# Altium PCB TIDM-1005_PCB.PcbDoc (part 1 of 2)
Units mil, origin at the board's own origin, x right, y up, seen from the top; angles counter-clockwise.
Board outline 3505 x 2975 mil, 2 copper layers (Top Layer, Bottom Layer), stack 62 mil thick; 159 components, 97 nets, 498 pads, 124 vias.
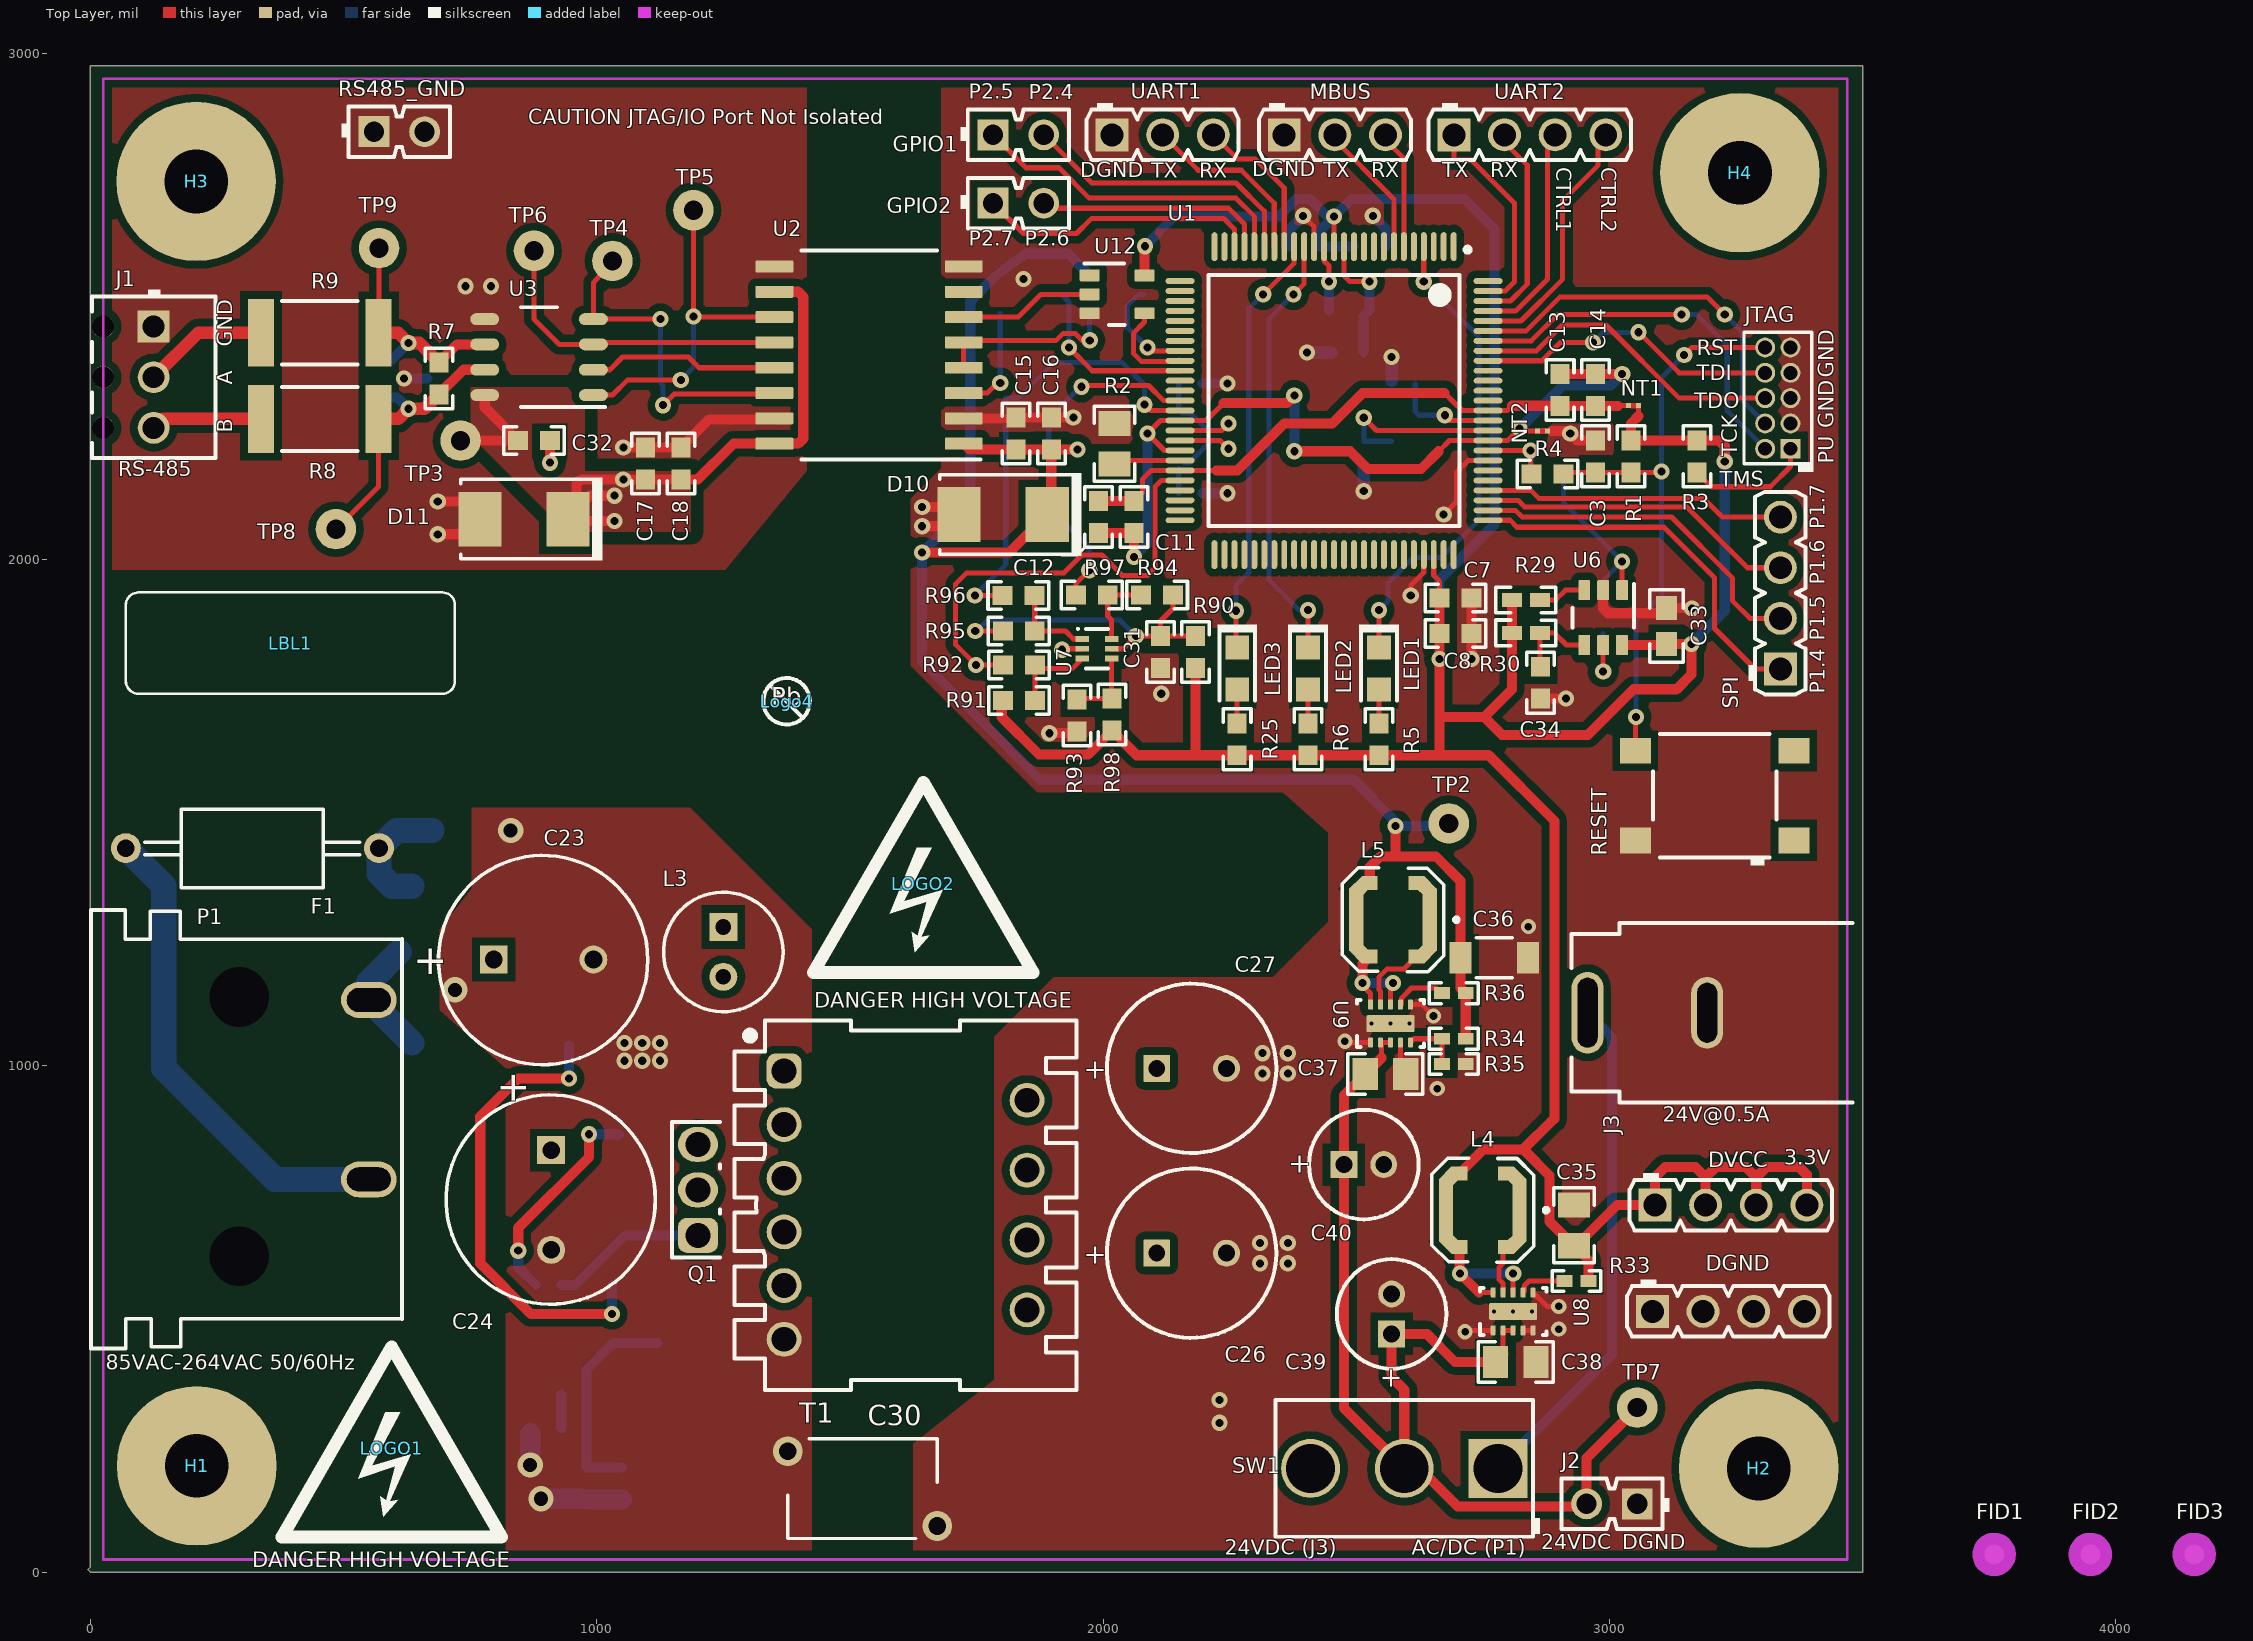
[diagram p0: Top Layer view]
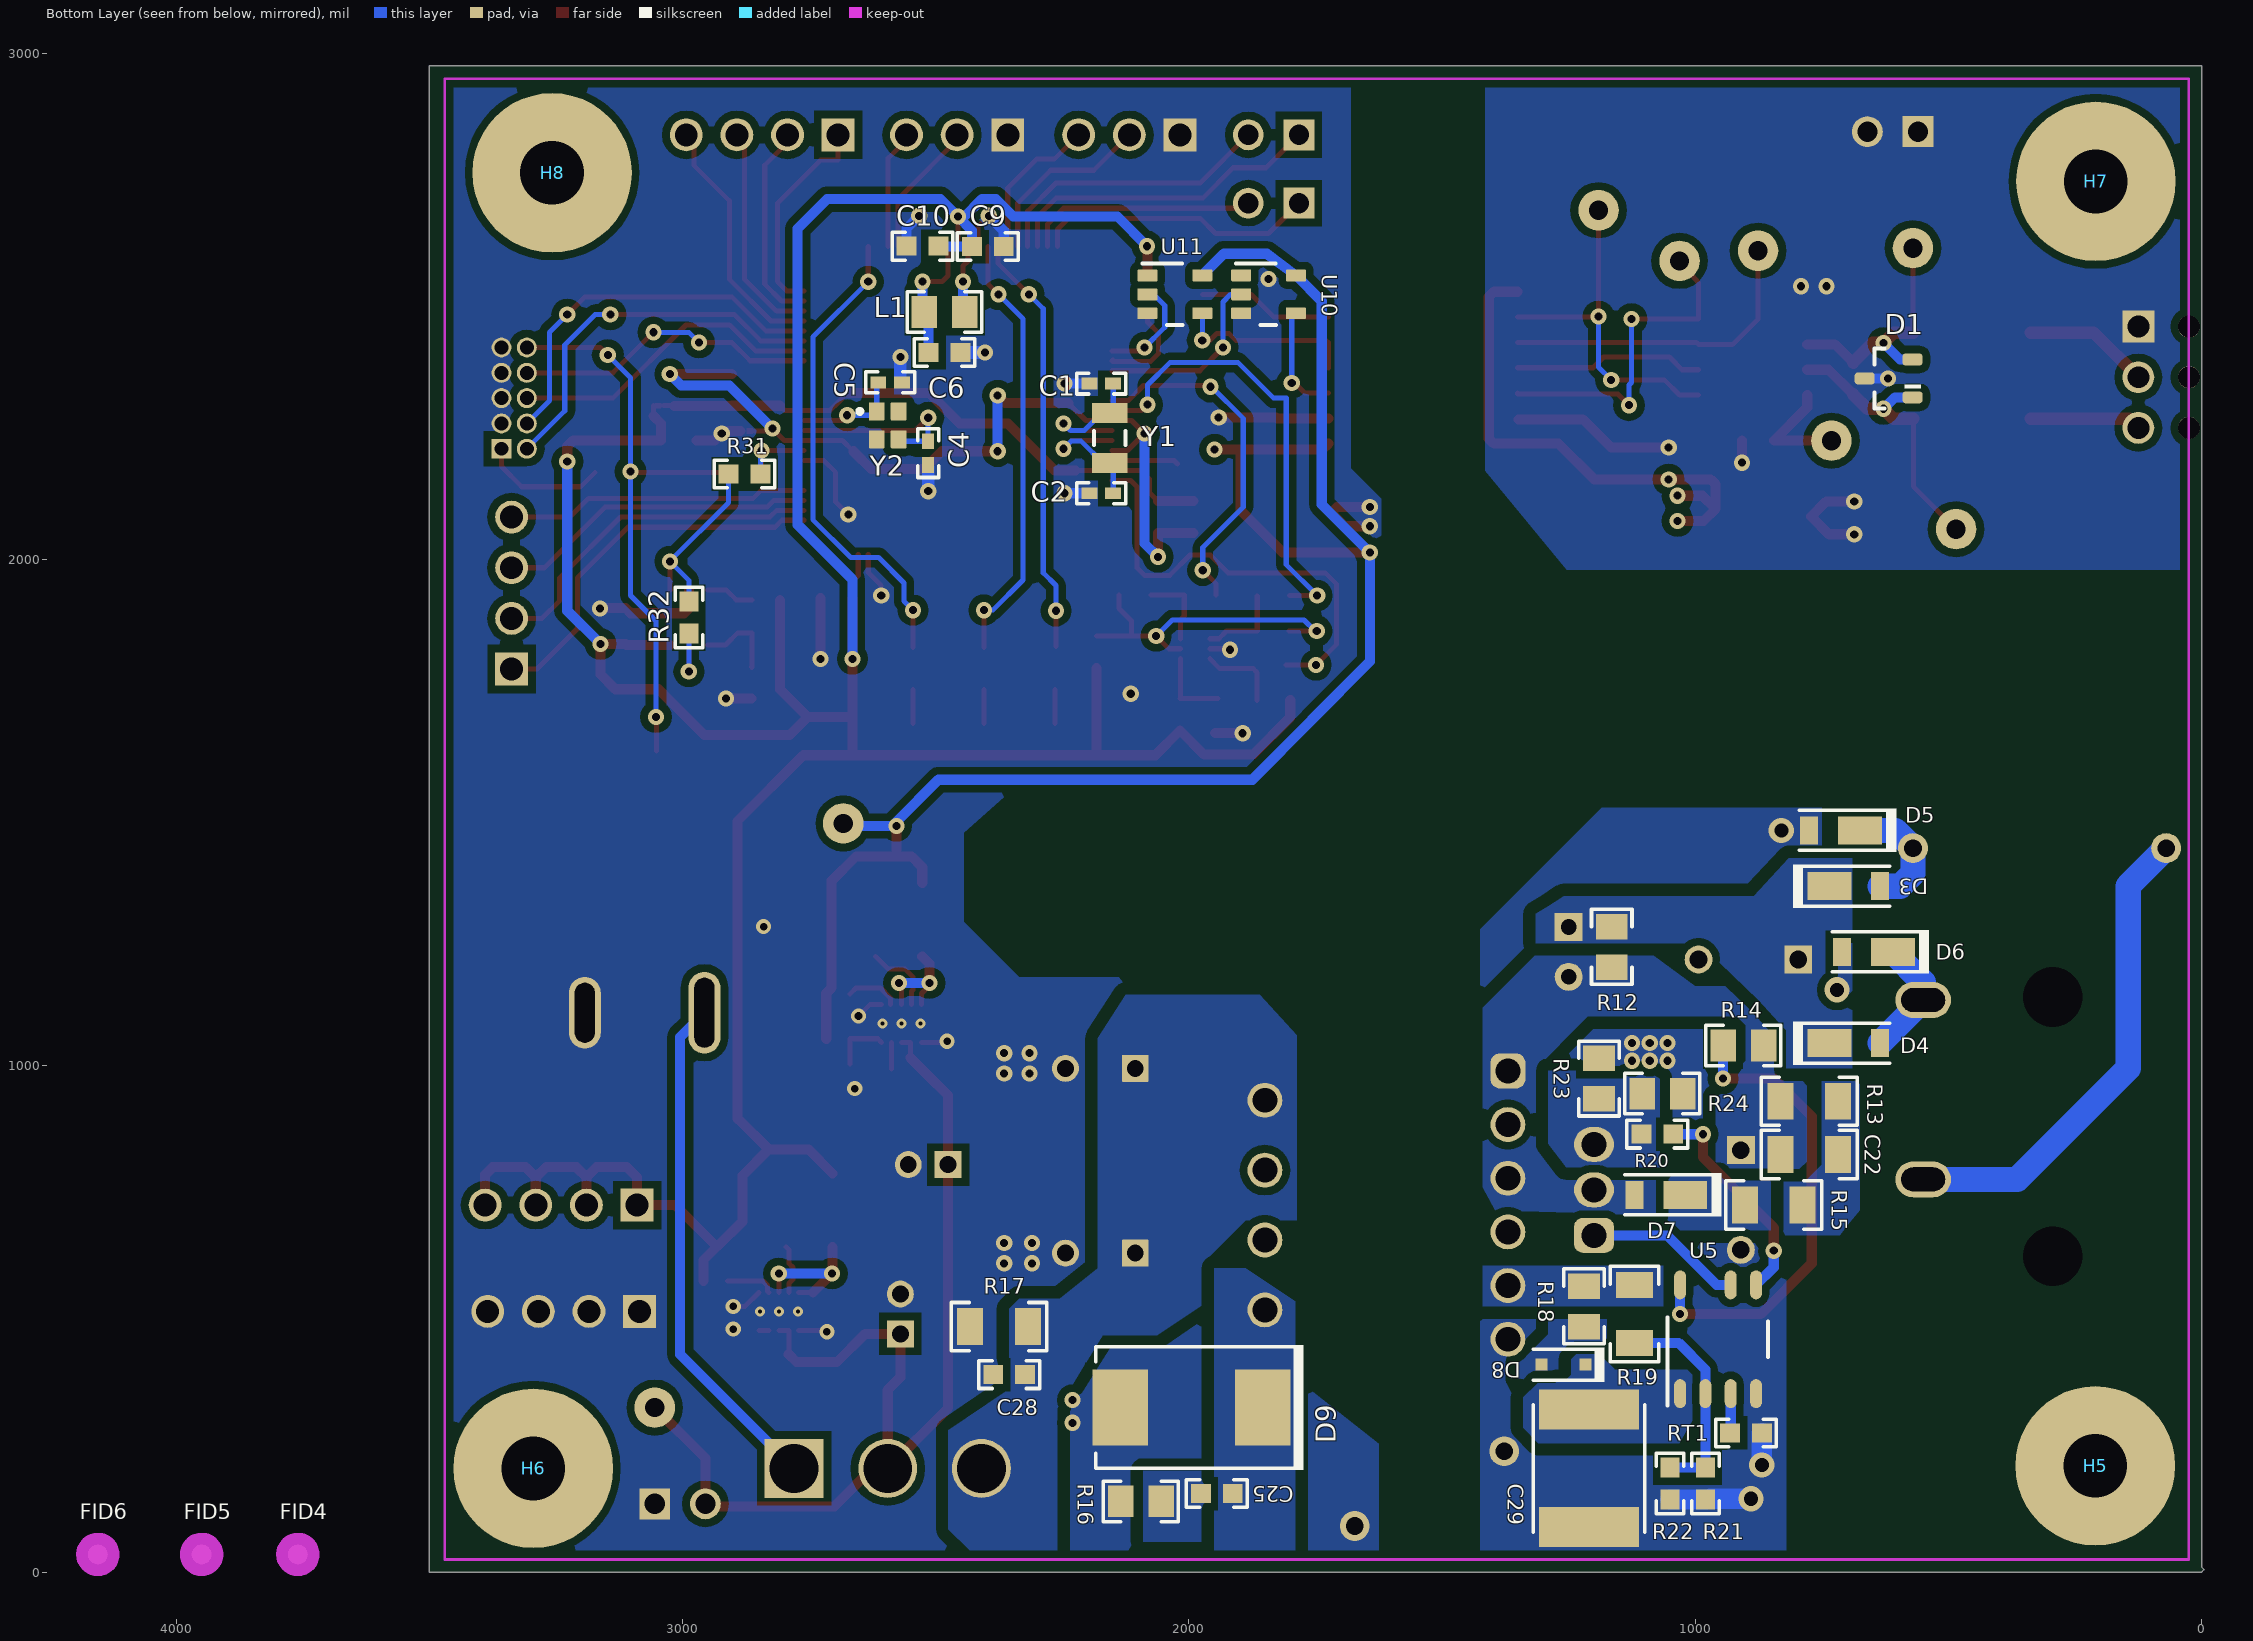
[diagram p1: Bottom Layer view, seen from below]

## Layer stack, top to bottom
Top Solder: solder mask 0.4, Solder Resist, Dk 3.5
Top Layer: signal copper 1.4
Dielectric1: core 59.2, FR-4, Dk 4.8
Bottom Layer: signal copper 1.4
Bottom Solder: solder mask 0.4, Solder Resist, Dk 3.5

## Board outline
-5,5 0,10 0,2975 3500,2975 3500,0 0,0

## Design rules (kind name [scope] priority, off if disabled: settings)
AcuteAngle [All] p1: minimum=4.50000000000000E+0001 checktracksonly=FALSE
AssemblyTestPointUsage [All] p1: valid=2
BoardOutlineClearance BoardOutlineClearance_MountingHoles [OnCopper and InComponentClass('Mounting Holes')] p1: gap=30
BoardOutlineClearance BoardOutlineClearance_Poly [OnCopper and IsPoly] p2: gap=25
BoardOutlineClearance [OnCopper and Not InComponentClass('Logo') and not InComponentClass('FiducialMark') and not InRegion(1000,500,4000,800) and not InPoly] p3: gap=55
Clearance mdViaVia [IsVia vs IsVia] p1: gap=7
Clearance mdPadVia [IsPad vs IsVia] p2: gap=7
Clearance mdPadPad [IsPad vs IsPad] p3: gap=7
Clearance mdWireVia [(InLayerClass('Signal Layers') AND IsTrack) vs IsVia] p4: gap=7
Clearance mdWirePad [(InLayerClass('Signal Layers') AND IsTrack) vs IsPad] p5: gap=7
Clearance mdWireWire [(InLayerClass('Signal Layers') AND IsTrack) vs (InLayerClass('Signal Layers') AND IsTrack)] p6: gap=7
Clearance [All] p7: gap=7 except(15: Arc-Poly Track-Poly SMDPad-Poly THPad-Poly Via-Poly Fill-Poly; 25: Poly-Poly)
ComponentClearance ComponentClearance_MountingHoles_FiducialMarks [InComponentClass('Mounting Holes') vs InComponentClass('FiducialMark')] p1: gap=50 collisioncheckmode=3 verticalgap=10 showdistances=FALSE
ComponentClearance ComponentClearance_Shunt [InComponentClass('Header') vs InComponentClass('Shunt')] p2: gap=0 collisioncheckmode=3 verticalgap=0 showdistances=FALSE
ComponentClearance ComponentClearance_Logo [InComponentClass('Logo')] p3: gap=0 collisioncheckmode=3 verticalgap=0 showdistances=FALSE
ComponentClearance ComponentClearance_ScrewToNut [(HasFootprint('NY PMS 440 0025 PH')) vs (HasFootprint('Keystone_1902C'))] p4: gap=5 collisioncheckmode=3 verticalgap=10 showdistances=FALSE
ComponentClearance ComponentClearance_MountingHoles [InComponentClass('Mounting Holes')] p5: gap=0 collisioncheckmode=3 verticalgap=100000 showdistances=FALSE
ComponentClearance ComponentClearance_SmallPassives [HasFootprint('0201*') or HasFootprint('0402*') or HasFootprint('0508') or HasFootprint('0603*') or HasFootprint('0612') or HasFootprint('0805*') or HasFootprint('0815*') or HasFootprint('0830*') or HasFootprint('1206*') or HasFootprint('1210*') or HasFootprint('1808*') or HasFootprint('1812*') or HasFootprint('1825*') or HasFootprint('2010*') or HasFootprint('2220*') or HasFootprint('2225*') or HasFootprint('2512*') or HasFootprint('2728*') or HasFootprint('3518*') vs HasFootprint('0201*') or HasFootprint('0402*') or HasFootprint('0508') or HasFootprint('0603*') or HasFootprint('0612') or HasFootprint('0805*') or HasFootprint('0815*') or HasFootprint('0830*') or HasFootprint('1206*') or HasFootprint('1210*') or HasFootprint('1808*') or HasFootprint('1812*') or HasFootprint('1825*') or HasFootprint('2010*') or HasFootprint('2220*') or HasFootprint('2225*') or HasFootprint('2512*') or HasFootprint('2728*') or HasFootprint('3518*')] p6: gap=14.96 collisioncheckmode=3 verticalgap=10 showdistances=FALSE
ComponentClearance ComponentClearance_THtoSMT [IsThruComponent vs IsSMTComponent] p7: gap=40 collisioncheckmode=3 verticalgap=30 showdistances=FALSE
ComponentClearance ComponentClearance_THtoTH [IsThruComponent vs IsThruComponent] p8: gap=30 collisioncheckmode=3 verticalgap=30 showdistances=FALSE
ComponentClearance [All] p9: gap=30 collisioncheckmode=3 verticalgap=10 showdistances=FALSE
DiffPairsRouting [All] p1: maxlimit=100 minlimit=10 mostfreqgap=10 toplayer_minwidth=15 toplayer_maxwidth=15 toplayer_prefwidth=15 bottomlayer_minwidth=15 bottomlayer_maxwidth=15 bottomlayer_prefwidth=15 maxuncoupledlength=1000
FabricationTestPointUsage TestPointUsage [All] p1: valid=2 allowmultiple=FALSE
FabricationTestpoint Testpoint [All] p1: side=3 testpointundercomponent=TRUE minsize=40 maxsize=100 preferedsize=60 minholesize=0 maxholesize=40 preferedholesize=32 testpointgrid=1 allowsidetop=TRUE allowsidebottom=TRUE usegrid=TRUE gridtolerance=0.01
FanoutControl Fanout_LCC [IsLCC] p1: bgadir=Out bgaviamode=Centered fanoutstyle=Auto fanoutdirection=Alternating viagrid=1 // Fanout_LCC (Default Rule)
FanoutControl Fanout_BGA [IsBGA] p2: bgadir=Out bgaviamode=Centered fanoutstyle=Auto fanoutdirection=Alternating viagrid=1 // Fanout_BGA (Default Rule)
FanoutControl Fanout_Default [All] p4: bgadir=Out bgaviamode=Centered fanoutstyle=Auto fanoutdirection=Alternating viagrid=1 // Fanout_Default (Default Rule)
FanoutControl Fanout_Small [(CompPinCount < 5)] p5: bgadir=Out bgaviamode=Centered fanoutstyle=Auto fanoutdirection=OutThenIn viagrid=1 // Fanout_Small (Default Rule)
Height [All] p1: minheight=0 maxheight=1200 prefheight=500
HoleSize [All] p1: absolutevalues=TRUE maxlimit=251 minlimit=7.87 maxpercent=80.000 minpercent=20.000
MinimumAnnularRing MinimumAnnularRing_ThermalPadVias [IsVia and InAnyComponent] p1: minimumring=5.91
MinimumAnnularRing [All] p2: minimumring=5
MinimumSolderMaskSliver MinimumSolderMaskSliver_Logo [InComponentClass('Logo') vs InComponentClass('Logo')] p1: minsoldermaskwidth=0.7
MinimumSolderMaskSliver [All] p2: minsoldermaskwidth=3.94
PlaneConnect [All] p1: planeconnectstyle=Direct reliefexpansion=10 reliefentries=4 reliefconductorwidth=10 reliefairgap=10
PolygonConnect PolygonConnect_Via [All vs IsVia] p1: connectstyle=Direct reliefconductorwidth=10 reliefentries=4 polygonreliefangle="90 Angle" airgapwidth=10
PolygonConnect PolygonConnect_1 [All] p2: connectstyle=Direct reliefconductorwidth=10 reliefentries=4 polygonreliefangle="90 Angle" airgapwidth=10
RoutingVias ThermalPadVias [IsVia and InAnyComponent] p1: holewidth=7.87 width=19.68 viastyle="Through Hole" minholewidth=7.87 minwidth=19.68 maxholewidth=12.99 maxwidth=23.62
RoutingVias [All] p2: holewidth=16 width=34 viastyle="Through Hole" minholewidth=7.87 minwidth=26 maxholewidth=40 maxwidth=65
SilkToBoardRegionClearance [Not ((IsComment or IsDesignator) And (Hide <> 'False')) and not InRegion(1000,500,4000,800)] p1:
SilkToSilkClearance SilkToSilkClearance_Pb-FreeLogo [(HasFootprint('Pb-Free_Overlay_Medium') OR HasFootprint('Pb-Free_Overlay_Small')) vs (HasFootprint('Pb-Free_Overlay_Medium') OR HasFootprint('Pb-Free_Overlay_Small'))] p1: silktosilkclearance=0
SilkToSilkClearance [All] p2: silktosilkclearance=4
SilkToSolderMaskClearance SilkToComponentPadClearance [(IsPad or IsFill or IsRegion) and InAnycomponent] p1: minsilkscreentomaskgap=3 clearancetoexposedcopper=TRUE
SilkToSolderMaskClearance "Silk to Solder Mask Opening" [All] p2: minsilkscreentomaskgap=1 clearancetoexposedcopper=FALSE
SolderMaskExpansion [All] p1: expansion=1.97
Width Width_1 [(InNet('24VDC') OR InNet('NetD6_2') OR InNet('NetD6_1') OR InNet('NetQ1_3') OR InNet('NetR18_1') OR InNet('NetQ1_1') OR InNet('NetR17_2') OR InNet('NetR16_2') OR InNet('NetR12_2')OR InNet('NetC22_1') OR InNet('NetC25_2') OR InNet('NetJ11_1') OR InNet('NetC19_1') OR InNet('NetC19_2') OR InNet('NetC29_2')) OR InNet('NetC25_1')] p1: maxlimit=40 minlimit=20 preferedwidth=20 minimp=50.000000 maximp=50.000000 favimp=50.000000
Width Width_PWR [InNet('PGND') OR InNet('NetF1_2') OR InNet('NetD2_2') OR InNet('NetD3_2') OR InNet('NetC23_1') OR InNet('NetC22_2') OR InNet('NetD4_2') OR InNet('NetD7_2')] p2: maxlimit=50 minlimit=30 preferedwidth=50 minimp=50.000000 maximp=50.000000 favimp=50.000000
Width Width_VCC [InNet('24VDCIN') OR InNet('24VDCOUT')OR InNet('DVCC')OR InNet('AVCC')OR InNet('5VDC') OR InNet('NetC17_1')OR InNet('NetR18_2') or InNet('NetR20_1') or InNet('NetR14_2')] p3: maxlimit=50 minlimit=10 preferedwidth=20 minimp=50.000000 maximp=50.000000 favimp=50.000000
Width [All] p4: maxlimit=40 minlimit=10 preferedwidth=10 minimp=50.000000 maximp=50.000000 favimp=50.000000
14 further rules are at their usual default settings.

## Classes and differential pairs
component class TIDM-1005_2: C15 C16 C17 C18 C31 C32 C33 C34 D1 D10 D11 J1 R7 R8 R9 R29 R30 R32 R90 R91 R92 R93 R94 R95 R96 R97 R98 RS485_GND TP2 TP3 TP4 TP5 TP6 TP8 TP9 U2 U3 U6 U7 U10 U11 U12
component class TIDM-1005-EVM_Hardware: !PCB FID1 FID2 FID3 FID4 FID5 FID6 H1 H2 H3 H4 H5 H6 H7 H8 LBL1 LOGO1 LOGO2 Logo4 ZZ1 ZZ2 ZZ3 ZZ4
component class "Mounting Holes": H1 H2 H3 H4
component class Label: LBL1
component class FiducialMark: FID1 FID2 FID3 FID4 FID5 FID6
component class AssemblyNote: ZZ1 ZZ2 ZZ3 ZZ4
component class TIDM-1005_3: C22 C23 C24 C25 C26 C27 C28 C29 C30 C35 C36 C37 C38 C39 C40 D3 D4 D5 D6 D7 D8 D9 F1 J2 J3 L3 L4 L5 P1 Q1 R12 R13 R14 R15 R16 R17 R18 R19 R20 R21 R22 R23 R24 R33 R34 R35 R36 RT1 SW1 T1 TP7 U5 U8 U9
component class Header: DGND DVCC GPIO1 GPIO2 J2 J9 J10 JTAG JTAG1 MBUS MBUS1 RS485_GND SPI SPI1 UART1 UART2
component class TIDM-1005_1: C1 C2 C3 C4 C5 C6 C7 C8 C9 C10 C11 C12 C13 C14 DGND DVCC GPIO1 GPIO2 J9 JTAG JTAG1 L1 LED1 LED2 LED3 MBUS NT1 NT2 R1 R2 R3 R4 R5 R6 R25 R31 RESET SPI U1 UART1 UART2 Y1 Y2

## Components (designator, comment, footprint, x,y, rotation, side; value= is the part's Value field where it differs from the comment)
C1 "C1005C0G1H220J050BA" 0402 2173.2,2347.47 r180 bottom
C2 "C1005C0G1H220J050BA" 0402 2173.2,2130.93 r180 bottom
C3 "06033C104KAT2A" 0603 2972.8,2203.81 r90 top
C4 "C1005C0G1H220J050BA" 0402 2515,2210 r90 bottom
C5 "C1005C0G1H220J050BA" 0402 2590,2350 r0 bottom
C6 "GRM188R71E474KA12D" 0603 2482.8,2408.81 r180 bottom
C7 "GRM188R6YA475KE15D" 0603 2696.3,1923.81 r180 top
C8 "GCM188R71H104KA57D" 0603 2696.3,1853.81 r0 top
C9 "GRM188R6YA475KE15D" 0603 2397.25,2617.94 r0 bottom
C10 "GCM188R71H104KA57D" 0603 2526.3,2618.81 r0 bottom
C11 "GRM188R6YA475KE15D" 0603 2061.3,2083.81 r90 top
C12 "GCM188R71H104KA57D" 0603 1991.3,2083.81 r270 top
C13 "GRM188R6YA475KE15D" 0603 2902.85,2334.79 r270 top
C14 "GCM188R71H104KA57D" 0603 2972.85,2334.79 r90 top
C15 "C0603C104J4RACTU" 0603 1827.8,2248.81 r90 top
C16 "C0603C106M9PACTU" 0603 1897.8,2248.81 r270 top
C17 "C0603C104J4RACTU" 0603 1096.09,2189.83 r90 top
C18 "C0603C106M9PACTU" 0603 1166.09,2189.83 r270 top
C22 "C3216C0G2J471J085AA" 1206 775,825 r0 bottom
C23 "UCS2G100MPD1TD" CAPPRD500W60D1000H2000 895,1210 r0 top
C24 "UCS2G100MPD1TD" CAPPRD500W60D1000H2000 910,735 r270 top
C25 "GRM188R72E221KW07D" 0603 1945,155 r180 bottom
C26 "UHE1V221MPD1TD" Nichicon_800x1500 2175,630 r0 top
C27 "UHE1V221MPD1TD" Nichicon_800x1500 2175,995 r0 top
C28 "0603YC104JAT2A" 0603 2355,390 r0 bottom
C29 "CKG57NX5R1E476M500JH" CKG57N 1210,205 r90 bottom
C30 "VY2471K29Y5SS63V7" VY2_750x500 1525,165 r180 top
C31 "06033C104JAT2A" 0603 2113.66,1817.31 r90 top
C32 "C0603C104J4RACTU" 0603 876.09,2234.83 r0 top
C33 "06033C104JAT2A" 0603M 3112.8,1868.81 r270 top
C34 "06035A151JAT2A" 0603 2864.29,1756.8 r270 top
C35 "GRM21BR60J226ME39L" 0805_HV 2930,685 r90 top
C36 "GRM31CR61A226KE19L" 1206_180 2772.72,1213.54 r0 top
C37 "GRM21BR61E225KA12L" 0805_HV 2557.72,983.54 r180 top
C38 "GRM21BR61E225KA12L" 0805_HV 2815,415 r180 top
C39 "ECA1HM220" Panasonic_500x1100 2570,510 r90 top
C40 "ECA1HM220" Panasonic_500x1100 2515,805 r0 top
D1 "CDSOT23-SM712" SOT-23 618.16,2357.72 r0 bottom
D3 "DFLR1600-7" PowerDI123 685,1355 r180 bottom
D4 "DFLR1600-7" PowerDI123 685,1045 r180 bottom
D5 "DFLR1600-7" PowerDI123 725,1465 r0 bottom
D6 "DFLR1600-7" PowerDI123 660,1225 r0 bottom
D7 "DFLR1600-7" PowerDI123 1070,745 r0 bottom
D8 "BAS20HT1G" SOD-323 1260,410 r0 bottom
D9 "MBRS3201T3G" SMC 1995,325 r0 bottom
D10 "1SMB5919BT3G" SMB 1802.8,2088.81 r180 top
D11 "1SMB5919BT3G" SMB 856.09,2079.83 r180 top
DGND "61300411121" WURTH_61300411121 3235,515 r0 top
DVCC "61300411121" WURTH_61300411121 3240,725 r0 top
F1 "0263002.MAT1L" FUSE_263 320,1430 r180 top
FID1 "Fiducial" Fiducial10-20 3760,35 r0 top
FID2 "Fiducial" Fiducial10-20 3950,35 r0 top
FID3 "Fiducial" Fiducial10-20 4155,35 r0 top
FID4 "Fiducial" Fiducial10-20 3760,35 r180 bottom
FID5 "Fiducial" Fiducial10-20 3950,35 r180 bottom
FID6 "Fiducial" Fiducial10-20 4155,35 r180 bottom
GPIO1 "TSW-102-07-T-S" Samtec_TSW-102-07-T-S 1832.8,2838.81 r0 top
GPIO2 "TSW-102-07-T-S" Samtec_TSW-102-07-T-S 1832.8,2703.81 r0 top
H1 "NY PMS 440 0025 PH" "NY PMS 440 0025 PH"#1 210,210 r0 top
H2 "NY PMS 440 0025 PH" "NY PMS 440 0025 PH"#1 3295,205 r0 top
H3 "NY PMS 440 0025 PH" "NY PMS 440 0025 PH"#2 870,3220 r0 top
H4 "NY PMS 440 0025 PH" "NY PMS 440 0025 PH"#1 3257.8,2763.81 r0 top
H5 "1902C" Keystone_1902C#1 210,210 r180 bottom
H6 "1902C" Keystone_1902C#1 3295,205 r180 bottom
H7 "1902C" Keystone_1902C#2 865,3185 r180 bottom
H8 "1902C" Keystone_1902C#1 3257.8,2763.81 r180 bottom
J1 "1725669" Phoenix_1725669 125,2360 r270 top
J2 "TSW-102-07-T-S" Samtec_TSW-102-07-T-S 3005,135 r180 top
J3 "PJ-037AH" CUI_PJ-037AH 3075,1105 r90 top
JTAG "GRPB052VWVN-RC" CONN_GRPB052VWVN-RC 3332.8,2318.81 r90 top
L1 "LQM21PN4R7NGR" IND_LQM18P_FH 2482.8,2488.81 r0 bottom
L3 "7447462221" WE-TI_5075 1250,1225 r270 top
L4 "LPS4018-103MRB" LPS4018 2750,715 r180 top
L5 "LPS4018-103MRB" LPS4018 2572.72,1288.54 r180 top
LBL1 "Size: 0.65\" x 0.20 \"" Label_650x200 395,1835 r0 top
LED1 "LTST-C170KRKT" LED_LTST-C170_Red 2545,1785 r90 top
LED2 "LTST-C170KSKT" LED_LTST-C170 2405,1785 r90 top
LED3 "LTST-C170TBKT" LTST-C170TBKT_Blue 2265,1785 r90 top
LOGO1 "DANGER HIGH VOLTAGE" IEC_HighVoltage_Medium 595,245 r0 top
LOGO2 "DANGER HIGH VOLTAGE" IEC_HighVoltage_Medium 1645,1360 r0 top
Logo4 "Pb-Free Symbol" Pb-Free_Overlay_Small 1375,1720 r0 top
MBUS "61300311121" WURTH_61300311121 2457.8,2838.81 r0 top
NT1 "Net-Tie" Net-Tie_10mil 3047.8,2303.81 r180 top net-tie
NT2 "Net-Tie" Net-Tie_10mil 2867.8,2253.81 r180 top net-tie
P1 "770W-X2/10" CONN_AC_770W-SERIES 420,880 r90 top
Q1 "STD5NM60-1" IPAK 1200,755 r90 top
R1 "ERA-3AEB104V" 0603 3042.8,2203.81 r90 top
R2 "RG2012P-913-B-T5" 0805_HV 2022.8,2228.81 r90 top
R3 "ERJ-3EKF1001V" 0603 3172.8,2203.81 r90 top
R4 "CRCW06030000Z0EA" 0603 2877.8,2168.81 r180 top
R5 "ERA-3AEB101V" 0603 2544.93,1645 r270 top
R6 "ERA-3AEB101V" 0603 2405,1645 r270 top
R7 "CRCW0603120RJNEA" 0603 688.16,2357.72 r90 top
R8 "CRCW251210R0FKEG" 2512 453.16,2277.72 r180 top
R9 "CRCW251210R0FKEG" 2512 453.16,2447.72 r180 top
R12 "MCU08050C1002FP500" 0805_HV 1165,1235 r270 bottom
R13 "RC1206FR-07330KL" 1206 775,930 r180 bottom
R14 "MCU08050C1003FP500" 0805_HV 905,1040 r0 bottom
R15 "RC1206FR-07120RL" 1206 845,725 r0 bottom
R16 "ERJ-P6WF47R0V" 0805_HV 2095,140 r0 bottom
R17 "ERJ-8ENF3902V" 1206 2375,485 r0 bottom
R18 "RC0805FR-072RL" 0805_HV 1220,525 r90 bottom
R19 "RC1206FR-07110KL" 1206 1120,510 r270 bottom
R20 "MCT06030C2200FP500" 0603 1075,865 r0 bottom
R21 "MCT06030C3302FP500" 0603 980,175 r270 bottom
R22 "CRCW0603560KFKEA" 0603 1050,175 r270 bottom
R23 "RC0805FR-072RL" 0805_HV 1190,975 r90 bottom
R24 "RL1220S-2R2-F" 0805_HV 1065,945 r180 bottom
R25 "ERA-3AEB101V" 0603 2264.93,1645 r270 top
R29 "CRCW040210K0FKED" 0402M 2835.24,1920.3 r180 top
R30 "CRCW040210K0FKED" 0402M 2835.24,1855.3 r180 top
R31 "CRCW06030000Z0EA" 0603 2877.8,2168.81 r180 bottom
R32 "CRCW06030000Z0EA" 0603 2987.8,1885.3 r270 bottom
R33 "CRCW0402100KFKED" 0402 2935,575 r0 top
R34 "CRCW04022M00FKED" 0402 2692.72,1053.54 r180 top
R35 "CRCW0402383KFKED" 0402 2692.72,1003.54 r0 top
R36 "CRCW0402100KFKED" 0402 2692.72,1143.54 r0 top
R90 "RC0603JR-070RL" 0603 2182.8,1817.31 r270 top
R91 "CRCW060310K0JNEA" 0603 1833.9,1721.9 r180 top
R92 "RC0603JR-070RL" 0603 1833.9,1791.9 r180 top
R93 "RC0603JR-070RL" 0603 1948.9,1691.9 r270 top
R94 "RC0603FR-074K7L" 0603 2106.8,1929.81 r0 top
R95 "RC0603FR-074K7L" 0603 1833.66,1858.81 r180 top
R96 "CRCW060310R0FKEA" 0603 1832.8,1928.81 r180 top
R97 "CRCW060310R0FKEA" 0603 1977.8,1929.81 r180 top
R98 "RC0603FR-074K7L" 0603 2017.8,1693.81 r270 top
RESET "430182080816" SW_430182080816 3207.8,1533.81 r180 top
RS485_GND "TSW-102-07-T-S" Samtec_TSW-102-07-T-S 610,2845 r0 top
RT1 "NCP18WF104F12RB" 0603 900,275 r180 bottom
SPI "61300411121" WURTH_61300411121 3337.8,1933.81 r90 top
SW1 "100SP3T1B1M1QEH" SW_100SP3T1B1M1QEH 2595,205 r180 top
T1 "RLTI-1223" Renco_RLTI-1223 1610,725 r0 top
TP2 "TESTPOINT" TESTPOINT 2682.8,1478.81 r0 top
TP3 "TESTPOINT" TESTPOINT 731.09,2234.83 r0 top
TP4 "TESTPOINT" TESTPOINT 1031.09,2589.83 r0 top
TP5 "TESTPOINT" TESTPOINT 1191.09,2689.83 r0 top
TP6 "TESTPOINT" TESTPOINT 876.09,2609.83 r0 top
TP7 "TESTPOINT" TESTPOINT 3055,325 r0 top
TP8 "TESTPOINT" TESTPOINT 485,2060 r0 top
TP9 "TESTPOINT" TESTPOINT 570,2615 r0 top
U1 "MSP432P401RIPZR" PZ0100A_N 2456.3,2313.81 r270 top
U2 "ISOW7841DWR" DW0016B_N 1537.8,2403.81 r180 top
U3 "THVD1500DR" D0008A_N 886.09,2399.83 r180 top
U5 "UCC28711DR" D0007A_N 955,460 r90 bottom
U6 "TPS3808G01DBVR" DBV0006A_N 2987.8,1885.3 r270 top
U7 "TMP102AIDRL" DRL0006A_N 1987.8,1823.81 r0 top
U8 "TPS62177DQCR" DQC0010A 2810,515 r90 top
U9 "TPS62175DQCR" DQC0010A 2567.72,1083.54 r90 top
U10 "SN74LV1T34DBVR" DBV0005A_N 1842.8,2523.81 r180 bottom
U11 "SN74LV1T34DBVR" DBV0005A_N 2027.8,2523.81 r180 bottom
U12 "SN74LV1T34DBVR" DBV0005A_N 2027.8,2523.81 r0 top
UART1 "61300311121" WURTH_61300311121 2117.8,2838.81 r0 top
UART2 "61300411121" WURTH_61300411121 2842.8,2838.81 r0 top
Y1 "FC-135R 32.7680KA-A3" Epson_FC-135 2156.43,2239.99 r270 bottom
Y2 "CX2016DB48000H0FLJC1" Kyocera_CX2016DB 2595,2265 r180 bottom
ZZ1 "This Assembly Note is for PCB labels only" AssemblyNoteLabel 30,3735 r0 top
ZZ2 "These assemblies are ESD sensitive, ESD precautions shall be observed." AssemblyNote 30,3615 r0 top
ZZ3 "These assemblies must be clean and free from flux and all contaminants. Use of no clean flux is not acceptable." AssemblyNote 30,3485 r0 top
ZZ4 "These assemblies must comply with workmanship standards IPC-A-610 Class 2, unless otherwise specified." AssemblyNote 30,3350 r0 top

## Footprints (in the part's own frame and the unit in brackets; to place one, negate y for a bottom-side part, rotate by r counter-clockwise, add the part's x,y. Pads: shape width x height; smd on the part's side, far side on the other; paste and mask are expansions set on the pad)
0402 [mm] "0402 from SM-752 data"
  rect 0.8x0.6 smd: 1(-0.6,0) 2(0.6,0)
  silkscreen extent -1.22,-0.52 1.22,0.52, body extent -0.55,-0.3 0.55,0.3, height 0.6
0402M [mm] "0402 from SM-752 data"
  rect 1x0.7 smd: 1(-0.7,0) 2(0.7,0)
  silkscreen extent -1.5,-0.64 1.51,0.65, body extent -0.55,-0.3 0.55,0.3, height 0.6
0603 [mm] "0603 from SM-752 data"
  rect 1x0.95 smd: 1(-0.8,0) 2(0.8,0)
  silkscreen extent -1.52,-0.69 1.52,0.69, body extent -0.87,-0.47 0.87,0.47, height 1
0603M [mm] "0603 from SM-752 data"
  rect 1.2x1.05 smd: 1(-0.9,0) 2(0.9,0)
  silkscreen extent -1.82,-0.84 1.82,0.84, body extent -0.87,-0.47 0.87,0.47, height 1
0805_HV [mil] "0805 with 30mil clearance between pads"
  rect 50x63 smd: 1(-40,0) 2(40,0)
  silkscreen extent -74,-40 74,40, body extent -43,-29 43,29, height 57
1206 [mm] "1206 from SM-752 data"
  rect 1.3x1.85 smd: 1(-1.45,0) 2(1.45,0)
  silkscreen extent -2.4,-1.21 2.4,1.21, body extent -1.7,-0.9 1.7,0.9, height 1.35
1206_180 [mm] "1206_180"
  rect 1.1x1.6 smd: 1(-1.7,0) 2(1.7,0)
  silkscreen extent -0.9,-1 0.9,1, body extent -1.75,-0.95 1.75,0.95, height 1.8
2512 [mm] "Chip Resistor, Body 6.3x3.2mm, IPC Medium Density"
  rect 1.3x3.4 smd: 1(-2.95,0) 2(2.95,0)
  silkscreen extent -1.9,-1.6 1.9,1.6, body extent -3.22,-1.67 3.22,1.67, height 0.71
AssemblyNote [mil] "Assembly Note"
AssemblyNoteLabel [mil] "Assembly Note for PCB Labels"
CAPPRD500W60D1000H2000 [mm] "Capacitor, Electrolytic, Radial; Body 10 x 20 mm (Dia.xH typ); Pin Spacing 5 mm (typ)"
  rect 1.4x1.4 hole 0.889: 1(-2.5,0)
  round 1.4 hole 0.889: 2(2.5,0)
  silkscreen extent -5.27,-5.27 5.22,5.22, body extent -5.21,-5.24 5.24,5.24, height 22.01
CKG57N [mm] "Chip Capacitor, Body 6.0x5.0x5.0mm,"
  rect 2x5 smd: 1(-2.95,0) 2(2.95,0)
  silkscreen extent -3.2,-2.8 3.2,2.8, body extent -3.3,-2.75 3.3,2.75, height 5.5
CONN_AC_770W-SERIES [mm] "Qualtek Electronics"
  oval 1.8x2.8 hole 1.2 slot 2.2 at 90 deg: 1(6.35,-3.3) 2(-2.65,-3.3)
  round 2 hole 3 unplated: MH1(6.5,3.2) MH2(-6.5,3.2)
  silkscreen extent -11.12,-4.97 10.87,10.63, body extent -11.05,-4.8 10.8,10.6, height 22
CONN_GRPB052VWVN-RC [mm] "SULLINS"
  rect 1x1 hole 0.7 mask+0.08: 1(-2.54,-0.635)
  round 1 hole 0.7 mask+0.08: 2(-2.54,0.635) 3(-1.27,-0.635) 4(-1.27,0.635) 5(0,-0.635) 6(0,0.635) 7(1.27,-0.635) 8(1.27,0.635) 9(2.54,-0.635) 10(2.54,0.635)
  silkscreen extent -3.7,-1.8 3.3,1.7, body extent -3.17,-1.7 3.17,1.7, height 4
CUI_PJ-037AH [mm] "Power Jack, 2mm, R/A, TH"
  oval 4.1x1.6 hole 1 slot 3.5 at 0 deg: 1(0,3)
  oval 3.6x1.6 hole 1 slot 3 at 0 deg: 2(0,-3)
  silkscreen extent -4.5,-10.3 4.5,3.8, body extent -4.5,-10.7 4.5,3.8, height 11
D0007A_N [mm] "SOIC, 7-Leads, Body 4.9x3.9mm, Pitch 1.27mm, IPC Medium Density"
  oval 1.45x0.6 smd: 1(-2.725,1.905) 2(-2.725,0.635) 3(-2.725,-0.635) 4(-2.725,-1.905) 5(2.725,-1.905) 6(2.725,-0.635) 8(2.725,1.905)
  silkscreen extent -3.32,-2.5 1.1,2.52, body extent -3.01,-2.45 3.01,2.45, height 1.75
D0008A_N [mm] "SOIC, 8-Leads, Body 4.9x3.9mm, Pitch 1.27mm, IPC Medium Density"
  oval 1.45x0.6 smd: 1(-2.725,1.905) 2(-2.725,0.635) 3(-2.725,-0.635) 4(-2.725,-1.905) 5(2.725,-1.905) 6(2.725,-0.635) 7(2.725,0.635) 8(2.725,1.905)
  silkscreen extent -3.3,-2.5 0.9,2.5, body extent -3,-2.45 3,2.45, height 1.63
DBV0005A_N [mm] "SOT23, 5-Leads, Body 2.9x1.6mm, Pitch 0.95mm, Lead Span 2.8mm, IPC Medium Density"
  rrect17% 1x0.6 smd: 1(-1.375,0.95) 2(-1.375,0) 3(-1.375,-0.95) 4(1.375,-0.95) 5(1.375,0.95)
  silkscreen extent -1.63,-1.55 0.38,1.55, body extent -1.42,-1.46 1.42,1.46, height 1.09
DBV0006A_N [mm] "SOT23, 6-Leads, Body 2.9x1.6mm, Pitch 0.95mm, Lead Span 2.8mm, IPC Medium Density"
  rrect17% 1x0.6 smd: 1(-1.375,0.95) 2(-1.375,0) 3(-1.375,-0.95) 4(1.375,-0.95) 5(1.375,0) 6(1.375,0.95)
  silkscreen extent -1.68,-1.55 0.5,1.55, body extent -1.42,-1.46 1.42,1.46, height 1.12
DQC0010A [mm] "SON, 10-Leads, Body 2.1x3.1mm, Pitch 0.5mm, Thermal Pad 2.4x0.8mm"
  rrect40% 0.5x0.25 smd: 1(-0.95,1) 2(-0.95,0.5) 3(-0.95,0) 4(-0.95,-0.5) 5(-0.95,-1) 6(0.95,-1) 7(0.95,-0.5) 8(0.95,0) 9(0.95,0.5) 10(0.95,1)
  rrect12% 0.8x1.08 on Top Paste: 11(0,0.64) 11(0,-0.64)
  rrect12% 0.84x2.4 smd paste-0.42: 11(0,0)
  silkscreen extent -1.17,-1.68 1.17,1.68, body extent -1,-1.5 1,1.5, height 0.77
DRL0006A_N [mm] "SOTFL, 6-Flat Leads, Body 1.2x1.6x0.6mm, Pitch 0.5mm, IPC Medium Density"
  rect 0.67x0.3 smd: 1(-0.74,0.5) 2(-0.74,0) 3(-0.74,-0.5) 4(0.74,-0.5) 5(0.74,0) 6(0.74,0.5)
  silkscreen extent -1,-1 0.55,1.05, body extent -0.65,-0.85 0.65,0.85, height 0.6
DW0016B_N [mm] "SOIC, 16-Leads, Body 10.5x7.6mm, Pitch 1.27mm, IPC Medium Density"
  rrect17% 1.9x0.6 smd: 1(-4.75,4.445) 2(-4.75,3.175) 3(-4.75,1.905) 4(-4.75,0.635) 5(-4.75,-0.635) 6(-4.75,-1.905) 7(-4.75,-3.175) 8(-4.75,-4.445) 9(4.75,-4.445) 10(4.75,-3.175) 11(4.75,-1.905) 12(4.75,-0.635) 13(4.75,0.635) 14(4.75,1.905) 15(4.75,3.175) 16(4.75,4.445)
  silkscreen extent -5.6,-5.25 3.4,5.25, body extent -5.17,-5.15 5.17,5.15, height 2.59
Epson_FC-135 [mm] "SMD, 2-Leads, Body 3.2x1.5mm"
  rect 1x1.8 smd: 1(-1.25,0) 2(1.25,0)
  silkscreen extent -0.35,-0.8 0.35,0.8, body extent -1.65,-0.8 1.65,0.8, height 0.9
Fiducial10-20 [mm]
  round 1 smd mask+0.5: 1(0,0)
  Top Layer keep-out circle w1.178: c0,0 r0.5
FUSE_263 [mm] "Littelfuse 263 series"
  round 1.5 hole 0.889: 1(-6.35,0) 2(6.35,0)
  silkscreen extent -5.39,-1.95 5.39,1.99, body extent -6.67,-1.97 6.67,1.97, height 3.92
IEC_HighVoltage_Medium [mil]
  silkscreen extent -217,-176 217,200
IND_LQM18P_FH [mil] "MuRata"
  rect 50x63 smd: 1(-40,0) 2(40,0)
  silkscreen extent -74,-40 74,40, body extent -43,-29 43,29, height 43
IPAK [mm] "IPAK"
  rrect50% 1.75x2 hole 1.25: 1(-2.28,0)
  oval 1.75x2 hole 1.25: 2(0,0) 3(2.28,0)
  silkscreen extent -3.4,-1.1 3.4,1.3, body extent -3.25,-0.99 3.25,1.31, height 9.66
Keystone_1902C#1 [mil] "Hex Standoff, 4-40 threaded, nylon"
  round 1 on Mech4: 0(0,0)
  body extent -145,-126 146,126, height 501
Keystone_1902C#2 [mil] "Hex Standoff, 4-40 threaded, nylon"
  round 1 on Mech4: 0(656.1,-438.1)
  body extent 511,-564 802,-312, height 501
Kyocera_CX2016DB [mm] "SMD, 4-Leads, Body 2x1.6mm"
  rrect12% 0.8x0.9 smd: 1(-0.55,0.7) 2(-0.55,-0.7) 3(0.55,-0.7) 4(0.55,0.7)
  silkscreen extent -1.5,0.6 -1.3,0.8, body extent -0.85,-1.05 0.85,1.05, height 0.45
Label_650x200 [mil] "Thermal Transfer Label"
  round 1 on Mech13: 0(0,0)
  silkscreen extent -325,-100 325,100, body extent -325,-100 325,100, height 1
LED_LTST-C170 [mm] "LITE-ON"
  rect 1.2x1.2 smd: 1(-1.05,0) 2(1.05,0)
  silkscreen extent -1.6,-1 2.2,1, body extent -1.05,-0.67 1.05,0.67, height 1.1
LED_LTST-C170_Red [mm] "LITE-ON"
  rect 1.2x1.2 smd: 1(-1.05,0) 2(1.05,0)
  silkscreen extent -1.6,-1 2.2,1, body extent -1.05,-0.67 1.05,0.67, height 1.1
LPS4018 [mil]
  rect 28x123 smd: 1(-72.5,0) 2(72.5,0)
  rect 35.5x28 smd rot 45: 1(-64,64) 2(64.5,-63.5)
  rect 35.5x28 smd rot 135: 1(-64,-64) 2(64,64)
  rect 31.5x28 smd: 1(-46,72.5) 1(-46,-72.5) 2(46,72.5) 2(46,-72.5)
  silkscreen extent -129,-102 101,102, body extent -81,-81 81,81, height 71
LTST-C170TBKT_Blue [mm] "LITE-ON"
  rect 1.2x1.2 smd: 1(-1.05,0) 2(1.05,0)
  silkscreen extent -1.6,-1 2.2,1, body extent -1.05,-0.67 1.05,0.67, height 1.2
Net-Tie_10mil [mil] "10mil net tie, no solder mask opening, no solder paste"
  rect 10x10 smd paste-5 mask-5: 1(-10,0) 2(10,0)
  Top Layer region: -6,5 6,5 6,-5 -6,-5
Nichicon_800x1500 [mm] "TH, 2-Leads, Dia 8mm, Pin Spacing 3.5mm"
  rrect7% 1.35x1.35 hole 0.85: 1(-1.75,0)
  round 1.35 hole 0.85: 2(1.75,0)
  silkscreen extent -4.25,-4.25 4.25,4.25, body extent -4.22,-4.24 4.24,4.24, height 16.51
"NY PMS 440 0025 PH"#1 [mm] "4-40 nylon screw and mounting hole"
  round 8 hole 3.2: 1(0,0)
  body extent -3.3,-3.3 3.3,3.3, height 2.69
"NY PMS 440 0025 PH"#2 [mm] "4-40 nylon screw and mounting hole"
  round 8 hole 3.2: 1(-16.792,-12.017)
  body extent -20.09,-15.32 -13.5,-8.72, height 2.69
Panasonic_500x1100 [mm] "TH, 2-Leads, Dia 5mm,  Lead Spacing 2mm"
  rect 1.35x1.35 hole 0.85: 1(-1,0)
  round 1.35 hole 0.85: 2(1,0)
  silkscreen extent -2.75,-2.75 2.75,2.75, body extent -2.73,-2.75 2.75,2.75, height 12.51
Pb-Free_Overlay_Small [mil]
  silkscreen extent -46,-46 46,46
Phoenix_1725669 [mm] "Terminal Block, 3x1, 2.54 mm, TH"
  rect 1.6x1.6 hole 1.1: 1(-2.54,0)
  round 1.6 hole 1.1: 2(0,0) 3(2.54,0)
  round 1.1 hole 1.1 unplated mask+0: 4(-2.54,-2.54) 5(0,-2.54) 6(2.54,-2.54)
  silkscreen extent -4.4,-3.1 4.04,3.1, body extent -4.04,-3.1 4.04,3.1, height 8.5
PowerDI123 [mm] "Diodes Inc recommended land pattern, document number DS30628 Rev. 6-2"
  rect 2.2x1.4 smd: 1(-1.275,0)
  rect 0.9x1.4 smd: 2(1.275,0)
  silkscreen extent -3.1,-1.09 1.76,1.09, body extent -2.37,-0.96 1.53,0.97, height 1
PZ0100A_N [mm] "TSQFP, 100-Leads, Body 16.2x16.2mm (max), Pitch 0.50mm, IPC Medium Density"
  oval 1.45x0.3 smd: 1(-7.725,6) 2(-7.725,5.5) 3(-7.725,5) 4(-7.725,4.5) 5(-7.725,4) 6(-7.725,3.5) 7(-7.725,3) 8(-7.725,2.5) 9(-7.725,2) 10(-7.725,1.5) 11(-7.725,1) 12(-7.725,0.5) 13(-7.725,0) 14(-7.725,-0.5) 15(-7.725,-1) 16(-7.725,-1.5) 17(-7.725,-2) 18(-7.725,-2.5) 19(-7.725,-3) 20(-7.725,-3.5) 21(-7.725,-4) 22(-7.725,-4.5) 23(-7.725,-5) 24(-7.725,-5.5) 25(-7.725,-6) 51(7.725,-6) 52(7.725,-5.5) 53(7.725,-5) 54(7.725,-4.5) 55(7.725,-4) 56(7.725,-3.5) 57(7.725,-3) 58(7.725,-2.5) 59(7.725,-2) 60(7.725,-1.5) 61(7.725,-1) 62(7.725,-0.5) 63(7.725,0) 64(7.725,0.5) 65(7.725,1) 66(7.725,1.5) 67(7.725,2) 68(7.725,2.5) 69(7.725,3) 70(7.725,3.5) 71(7.725,4) 72(7.725,4.5) 73(7.725,5) 74(7.725,5.5) 75(7.725,6)
  oval 0.3x1.45 smd: 26(-6,-7.725) 27(-5.5,-7.725) 28(-5,-7.725) 29(-4.5,-7.725) 30(-4,-7.725) 31(-3.5,-7.725) 32(-3,-7.725) 33(-2.5,-7.725) 34(-2,-7.725) 35(-1.5,-7.725) 36(-1,-7.725) 37(-0.5,-7.725) 38(0,-7.725) 39(0.5,-7.725) 40(1,-7.725) 41(1.5,-7.725) 42(2,-7.725) 43(2.5,-7.725) 44(3,-7.725) 45(3.5,-7.725) 46(4,-7.725) 47(4.5,-7.725) 48(5,-7.725) 49(5.5,-7.725) 50(6,-7.725) 76(6,7.725) 77(5.5,7.725) 78(5,7.725) 79(4.5,7.725) 80(4,7.725) 81(3.5,7.725) 82(3,7.725) 83(2.5,7.725) 84(2,7.725) 85(1.5,7.725) 86(1,7.725) 87(0.5,7.725) 88(0,7.725) 89(-0.5,7.725) 90(-1,7.725) 91(-1.5,7.725) 92(-2,7.725) 93(-2.5,7.725) 94(-3,7.725) 95(-3.5,7.725) 96(-4,7.725) 97(-4.5,7.725) 98(-5,7.725) 99(-5.5,7.725) 100(-6,7.725)
  silkscreen extent -7.7,-6.3 6.3,6.83, body extent -8.01,-8.01 8.01,8.01, height 1.6
Renco_RLTI-1223 [mm] "TH, 10-Leads, Body 730x675mil"
  rrect50% 1.75x1.75 hole 1.25: 1(-6.096,6.731)
  round 1.75 hole 1.25: 2(-6.096,4.039) 3(-6.096,1.346) 4(-6.096,-1.346) 5(-6.096,-4.039) 6(-6.096,-6.731) 7(6.096,-5.258) 8(6.096,-1.753) 9(6.096,1.753) 10(6.096,5.258)
  silkscreen extent -8.57,-9.27 8.57,9.27, body extent -8.57,-9.27 8.57,9.27, height 22.68
Samtec_TSW-102-07-T-S [mm] "Header, 2.54 mm, 2x1, Tin, TH"
  rect 1.55x1.55 hole 1.02: 1(-1.27,0)
  round 1.55 hole 1.02: 2(1.27,0)
  silkscreen extent -2.9,-1.27 2.54,1.27, body extent -2.54,-1.27 2.54,1.27, height 8.38
SMB [mil] "Molded Diode, 2-Leads, Body 5.4x3.6mm, IPC Medium Density, based on OnSemi component dimensions"
  rect 85x107.99 smd: 1(-87.01,0) 2(87.01,0)
  silkscreen extent -155,-82 125,82, body extent -106,-71 106,71, height 91
SMC [mil] "Molded Diode, 2-Leads, Body 6.9x5.8mm, IPC Medium Density, based on OnSemi component dimensions and land patterns"
  rect 110x150 smd: 1(-140.49,0) 2(140.49,0)
  silkscreen extent -221,-124 189,123, body extent -156,-116 156,116, height 91
SOD-323 [mm] "NXP recommended land pattern"
  rect 0.6x0.6 smd paste-0.05: 1(-1.1,0) 2(1.1,0)
  silkscreen extent -2.06,-0.86 1.53,0.86, body extent -1.3,-0.67 1.3,0.68, height 1.1
SOT-23 [mm] "SOT23, 3-Leads, Body 2.9x1.3mm, Pitch 0.95mm, Lead Span 2.5mm, IPC Medium Density"
  rrect50% 1x0.6 smd: 1(-1.2,0.95) 2(-1.2,-0.95) 3(1.2,0)
  silkscreen extent -1.63,-1.5 0.7,1.5, body extent -1.16,-1.45 1.21,1.45, height 1
SW_100SP3T1B1M1QEH [mm] "TH, 3-Leads, Body 12.7x6.86mm, Pitch 4.7mm"
  rect 2.95x2.95 hole 2.45: 1(-4.7,0)
  round 2.95 hole 2.45: 2(0,0) 3(4.7,0)
  silkscreen extent -6.8,-3.43 6.45,3.43, body extent -6.35,-3.43 6.35,3.43, height 28.87
SW_430182080816 [mm] "SMD, 4-Leads, Body 6.2x6.2mm"
  rect 1.55x1.3 smd: 1(-3.975,2.25) 2(-3.975,-2.25) 3(3.975,2.25) 4(3.975,-2.25)
  silkscreen extent -3.1,-3.1 3.1,3.5, body extent -4.5,-3.1 4.5,3.1, height 8
TESTPOINT [mil]
  round 80 hole 37.99: 1(0,0)
VY2_750x500 [mm] "Vishay"
  round 1.5 hole 0.889: 1(-3.75,1.875) 2(3.75,-1.875)
  silkscreen extent -3.75,-2.5 3.75,2.5, body extent -4.05,-2.5 4.05,2.5, height 10.5
WE-TI_5075 [mm] "Wurth WE-TI 5075"
  rect 1.4x1.4 hole 0.787: 1(-1.25,0)
  round 1.4 hole 0.787: 2(1.25,0)
  silkscreen extent -3,-3 3,3, body extent -3,-3 3,3, height 8.5
WURTH_61300311121 [mm] "Header, 2.54mm, 3x1, TH"
  rect 1.65x1.65 hole 1.15: 1(-2.54,0)
  round 1.65 hole 1.15: 2(0,0) 3(2.54,0)
  silkscreen extent -3.81,-1.27 3.81,1.6, body extent -3.81,-1.27 3.81,1.27, height 8.54
WURTH_61300411121 [mm] "Header, 2.54mm, 4x1, TH"
  rect 1.65x1.65 hole 1.15: 1(-3.81,0)
  round 1.65 hole 1.15: 2(-1.27,0) 3(1.27,0) 4(3.81,0)
  silkscreen extent -5.08,-1.27 5.08,1.6, body extent -5.08,-1.27 5.08,1.27, height 8.54

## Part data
C1 C2 C4 C5: "CAP, CERM, 22 pF, 50 V, +/- 5%, C0G/NP0, 0402"
C3: "CAP, CERM, 0.1 µF, 25 V, +/- 10%, X7R, 0603"
C6: "CAP, CERM, 0.47 µF, 25 V, +/- 10%, X7R, 0603"
C7 C9 C11 C13: "CAP, CERM, 4.7 µF, 35 V, +/- 10%, X5R, 0603"
C8 C10 C12 C14: "CAP, CERM, 0.1 µF, 50 V, +/- 10%, X7R, 0603"
C15 C17 C32: "CAP, CERM, 0.1uF, 16V, +/-5%, X7R, 0603"
C16 C18: "CAP, CERM, 10 µF, 6.3 V, +/- 20%, X5R, 0603"
C22: "CAP, CERM, 470 pF, 630 V, +/- 5%, C0G/NP0, 1206"
C23 C24: "CAP, AL, 10 µF, 400 V, +/- 20%, TH"
C25: "CAP, CERM, 220 pF, 250 V, +/- 10%, X7R, 0603"
C26 C27: "CAP, AL, 220 µF, 35 V, +/- 20%, TH"
C28: "CAP, CERM, 0.1 µF, 16 V, +/- 5%, X7R, 0603"
C29: "CAP, CERM, 47 µF, 25 V, +/- 20%, X5R, 6x5x5mm"
C30: "CAP, CERM, 470 pF, 300 V, +/- 10%, VY2, 5x7.5 mm"
C31: "CAP, CERM, 0.1 µF, 25 V, +/- 5%, X7R, 0603"
C33: "CAP, CERM, 0.1uF, 25V, +/-5%, X7R, 0603"
C34: "CAP, CERM, 150 pF, 50 V, +/- 5%, C0G/NP0, 0603"
C35: "CAP, CERM, 22 µF, 6.3 V, +/- 20%, X5R, 0805"
C36: "CAP, CERM, 22 µF, 10 V, +/- 10%, X5R, 1206"
C37 C38: "CAP, CERM, 2.2 µF, 25 V, +/- 10%, X5R, 0805"
C39 C40: "CAP, AL, 22 µF, 50 V, +/- 20%, TH"
D1: "Diode, TVS, Bi, 7 V, SOT-23"
D3 D4 D5 D6 D7: "Diode, Standard Recovery Rectifier, 600 V, 1 A, PowerDI123"
D8: "Diode, Switching, 200 V, 0.2 A, AEC-Q101, SOD-323"
D9: "Diode, Schottky, 200 V, 3 A, SMC"
D10 D11: "Diode, Zener, 5.6 V, 550 mW, SMB"
DGND DVCC SPI UART2: "Header, 2.54 mm, 4x1, Gold, TH"
F1: "Fuse, 2 A, 250 VAC, TH"
FID1 FID2 FID3 FID4 FID5 FID6: "Fiducial mark.  There is nothing to buy or mount."
GPIO1 GPIO2 J2 RS485_GND: "Header, 2.54 mm, 2x1, Tin, TH"
H1 H2 H3 H4: "Machine Screw, Round, #4-40 x 1/4, Nylon, Philips panhead"
H5 H6 H7 H8: "Standoff, Hex, 0.5\"L #4-40 Nylon"
J1: "Terminal Block, 3x1, 2.54 mm, TH"
J3: "Power Jack, 2mm, R/A, TH"
JTAG: "Header, 50mil, 5x2, Gold, TH"
L1: library part LQM21PN1R0MGH, "Inductor, Multilayer, Ferrite, 4.7 µH, 2 A, 0.08 ohm, SMD"
L3: "Inductor, Unshielded Drum Core, Ferrite, 220 µH, 0.5 A, 0.96 ohm, TH"
L4 L5: "Inductor, Shielded Drum Core, Ferrite, 10 µH, 1.25 A, 0.18 ohm, SMD"
LBL1: library part THT-14-423-10, "Thermal Transfer Printable Labels, 0.650\" W x 0.200\" H - 10,000 per roll"
LED1: "LED, Red, SMD"
LED2: "LED, Yellow , SMD"
LED3: "LED, Blue, SMD"
LOGO1 LOGO2: library part IEC_HighVoltage, "IEC 61010-1 High Voltage Warning"
Logo4: library part Pb-Free
MBUS UART1: "Header, 2.54 mm, 3x1, Gold, TH"
NT1 NT2: "Single point connection between nets."
P1: "AC Receptacle, 2.5A, R/A, TH"
Q1: "MOSFET, N-CH, 650 V, 5 A, IPAK"
R1: "RES, 100 k, 0.1%, 0.1 W, 0603"
R2: "RES, 91.0 k, 0.1%, 0.125 W, 0805"
R3: "RES, 1.00 k, 1%, 0.1 W, 0603"
R4 R31 R32: "RES, 0 ohm, 5%, 0.1W, 0603"
R5 R6 R25: "RES, 100, 0.1%, 0.1 W, 0603"
R7: "RES, 120 ohm, 5%, 0.1W, 0603"
R8 R9: "RES, 10.0, 1%, 1 W, AEC-Q200 Grade 0, 2512"
R12: "RES, 10.0 k, 1%, 0.2 W, 0805"
R13: "RES, 330 k, 1%, 0.25 W, 1206"
R14: "RES, 100 k, 1%, 0.2 W, 0805"
R15: "RES, 120, 1%, 0.25 W, 1206"
R16: "RES, 47.0, 1%, 0.5 W, AEC-Q200 Grade 0, 0805"
R17: "RES, 39.0 k, 1%, 0.25 W, AEC-Q200 Grade 0, 1206"
R18 R23: "RES, 2.00, 1%, 0.125 W, 0805"
R19: "RES, 110 k, 1%, 0.25 W, 1206"
R20: "RES, 220, 1%, 0.125 W, 0603"
R21: "RES, 33.0 k, 1%, 0.125 W, 0603"
R22: "RES, 560 k, 1%, 0.1 W, AEC-Q200 Grade 0, 0603"
R24: "RES, 2.20, 1%, 0.333 W, 0805"
R29 R30: "RES, 10.0k ohm, 1%, 0.063W, 0402"
R33 R36: "RES, 100 k, 1%, 0.063 W, 0402"
R34: "RES, 2.00 M, 1%, 0.063 W, 0402"
R35: "RES, 383 k, 1%, 0.063 W, 0402"
R90 R92 R93: "RES, 0, 5%, 0.1 W, 0603"
R91: "RES, 10 k, 5%, 0.1 W, 0603"
R94 R95 R98: "RES, 4.70 k, 1%, 0.1 W, 0603"
R96 R97: "RES, 10.0, 1%, 0.1 W, 0603"
RESET: "Switch, Tactile, SPST-NO, 0.05A, 12V, SMD"
RT1: "Thermistor NTC, 100k ohm, 1%, 0603"
SW1: "Switch, Toggle SPDT 5A, 120V, TH"
T1: "Transformer, 720 uH, TH"
TP2 TP3 TP4 TP5 TP6 TP7 TP8 TP9: "TEST POINT.  No entry in BOM."
U1: "Mixed-Signal Microcontroller, PZ0100A (LQFP-100)"
U2: "ISOW7841DW, DW0016B (SOIC-16)"
U3: "250 kbps RS-485 Transceivers With ±12-kV IEC ESD Protection, D0008A (SOIC-8)"
U5: "Constant-Voltage, Constant-Current Controller With Primary-Side Regulation, D0007A (SOIC-7)"
U6: "Low Quiescent Current, Programmable-Delay Supervisory Circuit, DBV0006A (SOT-6)"
U7: "Low Power Digital Temperature Sensor With SMBus/Two-Wire Serial Interface in SOT563, DRL0006A"
U8 U9: "28V, 0.5A Step-Down Converter with SNOOZE Mode, DQC0010A (WSON-10)"
U10 U11 U12: "Single Power Supply BUFFER Logic Level Shifter (no enable), DBV0005A (SOT-5)"
Y1: library part X1A0001410014, "Crystal, 32.768 KHz, 12.5 pF, SMD"
Y2: "Crystal, 48MHz, 12pF, SMD"
ZZ1: library part AssemblyNoteLabel
ZZ2 ZZ3 ZZ4: library part AssemblyNote

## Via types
v1: diameter 32, hole 16, Top Layer to Bottom Layer, tented both sides, 88 vias
v2: diameter 32, hole 16, Top Layer to Bottom Layer, 19 vias
v3: diameter 30, hole 15, Top Layer to Bottom Layer, 7 vias
v4: diameter 19.68, hole 7.87, Top Layer to Bottom Layer, 6 vias
v5: diameter 50, hole 28, Top Layer to Bottom Layer, tented both sides, 3 vias
v6: diameter 50, hole 28, Top Layer to Bottom Layer, 1 vias

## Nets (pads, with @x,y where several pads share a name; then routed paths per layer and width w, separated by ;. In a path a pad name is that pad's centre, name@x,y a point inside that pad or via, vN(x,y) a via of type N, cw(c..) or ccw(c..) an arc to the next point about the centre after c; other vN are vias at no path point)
5VDC: C15.1 C16.2 C36.1 D10.1 L5.2 R34.1 R36.2 TP2.1 U2.1 U9.8 U9.10 U10.5 U11.5 | length 3658.8
  Top Layer w10: v2@2512.72,1158.54 2528.35,1142.91 U9.10@2528.35,1120.94 ; U9.8@2567.72,1120.94 v2@2567.72,1158.54
  Top Layer w20: v2(1642.8,2013.81) 1814.8,2013.81 D10.1@1889.8,2088.81 1897.8,2096.8 C16.2@1897.8,2217.31 ; U2.1@1724.8,2228.81 1736.3,2217.31 C15.1@1827.8,2217.31 C16.2@1897.8,2217.31 ; v2(1949.29,2217.31) C16.2@1897.8,2217.31 ; v2(2512.72,1163.54) 2512.72,1202.04 L5.2@2526.72,1216.04 ; L5.2@2526.72,1361.04 2526.72,1392.54 2547.72,1413.54 2657.72,1413.54 2705.79,1365.47 C36.1@2705.79,1213.54 2705.79,1154.09 R36.2@2716.34,1143.54 2716.34,1123.54 R34.1@2716.34,1053.54 ; 2577.8,1415.75 v2(2577.8,1473.81)
  Bottom Layer w20: U11.5@1973.66,2561.21 1931.06,2603.81 1846.26,2603.81 U10.5@1788.66,2561.21 1737.8,2510.34 1737.8,2108.81 v2(1642.8,2013.81) 1642.8,1798.81 1875,1565 2495,1565 v2@2577.8,1482.2 ; v2(2512.72,1163.54) v2(2572.72,1163.54) ; v2(2577.8,1473.81) TP2.1@2677.8,1473.81
24VDC: C26.1 C27.1 C28.1 R17.1 SW1.3 T1.10
24VDCOUT: C37.2 C38.2 C39.1 C40.1 J2.2 SW1.2 TP7.1 U8.2 U8.3 U9.2 U9.3 | length 2129.3
  Top Layer w10: 2550.27,1016.09 2550.27,1046.14 U9.3@2567.72,1046.14 ; C38.2@2790.32,430.32 U8.2@2790.32,477.6 U8.3@2810,477.6
  Top Layer w20: 2550.27,1016.09 C37.2@2517.72,983.54 2475.63,941.46 C40.1@2475.63,805 2475.63,324.37 SW1.2@2595,205 2595,360 2570,385 C39.1@2570,470.63 2639.37,470.63 2695,415 C38.2@2775,415 C38.2@2790.32,430.32 ; SW1.2@2624.86,205 2699.93,129.93 2955,129.93 J2.2@2955,135 2955,225 TP7.1@3055,325
AGND: C11.1 C12.2 C13.1 C14.2 NT2.2 U1.40 U1.43 U1.84 | length 1779.9
  Top Layer w10: U1.43@2152.17,2215.38 2121.22,2215.38 v1(2087.8,2248.81) 2113.43,2274.44 U1.40@2152.17,2274.44 2203.43,2274.44 2237.8,2308.81 ; 2662.8,2213.81 2684.06,2235.07 U1.84@2760.43,2235.07 2799.06,2235.07 v1(2822.8,2258.81) 2827.8,2253.81 NT2.2@2857.8,2253.81
  Top Layer w20: C12.2@1991.3,2052.31 C11.1@2061.3,2052.31 v1(2061.3,2005.3) ; 2237.8,2308.81 2362.8,2308.81 v1(2377.8,2323.81) ; v1(2377.8,2213.81) 2487.8,2213.81 2522.8,2178.81 2627.8,2178.81 2662.8,2213.81 ; C13.1@2902.85,2366.29 C14.2@2972.85,2366.29 v1(3025.28,2366.29)
  Bottom Layer w20: v1(2061.3,2005.3) 2087.8,2031.8 v1(2087.8,2248.81) ; v1(2377.8,2213.81) v1(2377.8,2323.81) ; v1(2822.8,2258.81) 2907.8,2343.81 3002.8,2343.81 v1(3025.28,2366.29)
AVCC: C11.2 C12.1 C13.2 C14.1 NT1.2 U1.45 U1.87 | length 1168.8
  Top Layer w10: C11.2@2061.3,2115.3 2077.8,2131.8 2077.8,2158.81 2095,2176.01 U1.45@2152.17,2176.01 2224.1,2176.01 ; 2674.74,2328.81 2693.24,2310.31 2709.44,2294.12 U1.87@2760.43,2294.12 2798.11,2294.12 2807.8,2303.81 ; 3017.8,2303.81 NT1.2@3037.8,2303.81
  Top Layer w20: C12.1@1991.3,2115.3 C11.2@2061.3,2115.3 ; 2224.1,2176.01 2265,2176.01 2357.8,2268.81 2452.8,2268.81 2512.8,2328.81 2674.74,2328.81 ; 2807.8,2303.81 2902.34,2303.81 C13.2@2902.85,2303.3 C14.1@2972.85,2303.3 3017.29,2303.3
